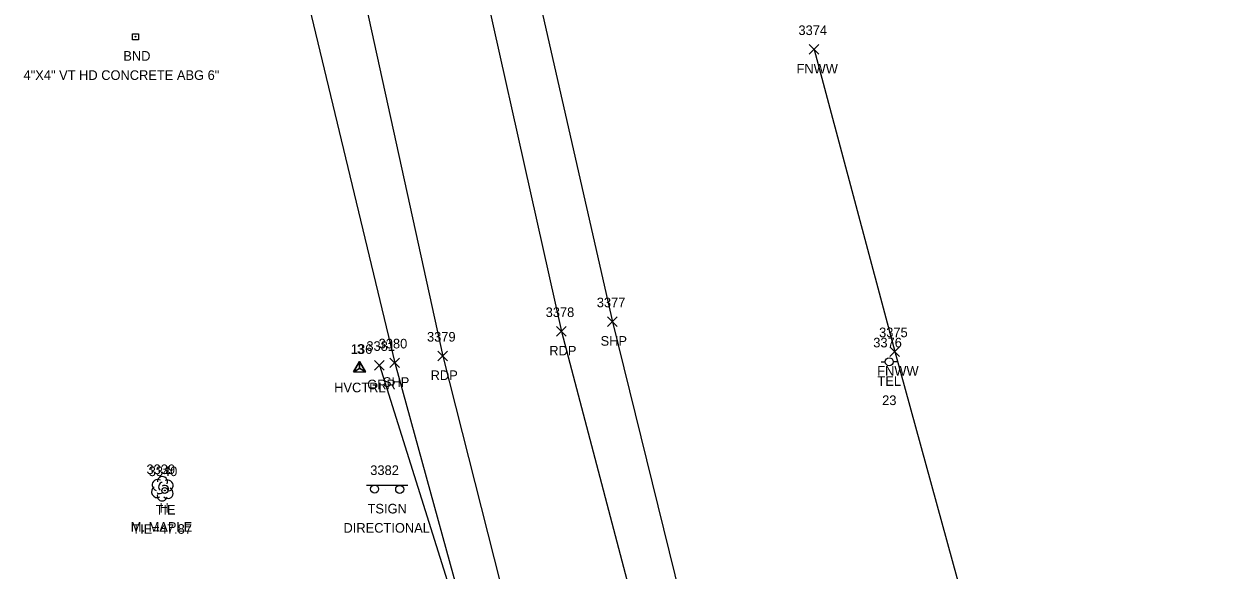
# Model space of a CAD drawing. Extents: x 1443071 to 1445292, y 614024 to 622563.
# Drawn here: x 1444456.9 to 1444705, y 615329.4 to 615443 of the extents above; entities that cross this region are included whole.
import ezdxf

# ---------------------------------------------------------------- set-up
doc = ezdxf.new("R2010")
doc.units = 0
for name, color, linetype in [('C_A', 7, 'Continuous'), ('C_C', 7, 'Continuous'), ('C_I', 7, 'Continuous'), ('CBP', 7, 'Continuous'), ('CPSM', 7, 'Continuous'), ('L_A', 7, 'Continuous'), ('L_C', 7, 'Continuous'), ('L_I', 7, 'Continuous'), ('L_TIC', 7, 'Continuous'), ('LFNC', 7, 'Continuous'), ('LTD', 7, 'Continuous'), ('M_A', 7, 'Continuous'), ('M_C', 7, 'Continuous'), ('MHBP', 7, 'Continuous'), ('P_A', 7, 'Continuous'), ('P_I', 7, 'Continuous'), ('P_TIC', 7, 'Continuous'), ('PET', 7, 'Continuous'), ('PSP', 7, 'Continuous'), ('R_A', 7, 'Continuous'), ('R_I', 7, 'Continuous'), ('R_TIC', 7, 'Continuous'), ('RGR', 7, 'Continuous'), ('S_A', 7, 'Continuous'), ('S_C', 7, 'Continuous'), ('S_I', 7, 'Continuous'), ('SSGN', 7, 'Continuous'), ('U_A', 7, 'Continuous'), ('U_C', 7, 'Continuous'), ('U_I', 7, 'Continuous'), ('UP', 7, 'Continuous')]:
    doc.layers.add(name, color=color, linetype=linetype)

msp = doc.modelspace()

# ---------------------------------------------------------------- linework, layer by layer
at = {"layer": 'CBP'}
for radius in [0.625, 0.0833]:
    msp.add_circle((1444486.26, 615345.94), radius, dxfattribs=at)
at = {"layer": 'CPSM'}
for p, q in [((1444525.55, 615370.66), (1444526.8, 615372.82)), ((1444525.55, 615370.66), (1444526.8, 615371.38)), ((1444525.57, 615370.66), (1444526.82, 615372.82)), ((1444525.57, 615370.66), (1444526.82, 615371.38)), ((1444528.05, 615370.66), (1444526.8, 615372.82)), ((1444526.8, 615371.38), (1444526.8, 615372.82)), ((1444526.8, 615371.38), (1444526.8, 615371.38)), ((1444526.8, 615371.38), (1444528.05, 615370.66)), ((1444528.07, 615370.66), (1444526.82, 615372.82)), ((1444526.82, 615371.38), (1444526.82, 615372.82)), ((1444526.82, 615371.38), (1444526.82, 615371.38)), ((1444526.82, 615371.38), (1444528.07, 615370.66)), ((1444525.55, 615370.66), (1444528.05, 615370.66)), ((1444525.57, 615370.66), (1444528.07, 615370.66))]:
    msp.add_line(p, q, dxfattribs=at)
at = {"layer": 'L_TIC'}
for points in [[(1444620.37, 615436.71), (1444622.37, 615438.71)], [(1444622.37, 615436.71), (1444620.37, 615438.71)], [(1444637.15, 615373.84), (1444639.15, 615375.84)], [(1444639.15, 615373.84), (1444637.15, 615375.84)]]:
    msp.add_lwpolyline(points, dxfattribs=at)
at = {"layer": 'LFNC'}
msp.add_lwpolyline([(1444621.37, 615437.71), (1444638.15, 615374.84), (1444654.37, 615315.72), (1444673.95, 615252.52), (1444691.33, 615200.58), (1444701.12, 615169.21), (1444682.74, 615145.08)], dxfattribs=at)
at = {"layer": 'LTD'}
msp.add_line((1444485.72, 615346.36), (1444485.72, 615346.36), dxfattribs=at)
msp.add_line((1444485.72, 615346.36), (1444485.72, 615346.36), dxfattribs=at)
msp.add_arc((1444485.77, 615347.79), 1.05, 335.5272, 180.9563, dxfattribs=at)
for centre, major_axis, ratio, start_param, end_param in [((1444484.64, 615345.65), (0.58, -1.04), 0.959034, 3.141593, 6.283185), ((1444484.93, 615347.02), (1.21, -0.51), 0.895232, 1.570796, 4.712389), ((1444485.51, 615346.81), (-0.208, -0.792), 0.645439, 3.141593, 6.283185), ((1444486.22, 615346.19), (-0.5, 0.667), 0.989748, 3.141593, 6.283185), ((1444486.72, 615345.52), (-1.09, 0.79), 0.841452, 1.570796, 4.712389), ((1444486.76, 615346.94), (-1.14, -0.48), 0.949671, 1.570796, 4.712389), ((1444485.72, 615344.86), (0.26, 1.06), 0.942809, 1.570796, 4.712389), ((1444485.26, 615345.61), (-0.625, -0.083), 0.423636, 0, 3.141593)]:
    msp.add_ellipse(centre, major_axis=major_axis, ratio=ratio, start_param=start_param, end_param=end_param, dxfattribs=at)
at = {"layer": 'MHBP'}
msp.add_lwpolyline([(1444479.51, 615440.99), (1444480.76, 615440.99), (1444480.76, 615439.74), (1444479.51, 615439.74)], close=True, dxfattribs=at)
msp.add_circle((1444480.14, 615440.37), 0.0833, dxfattribs=at)
at = {"layer": 'P_TIC'}
for points in [[(1444578.41, 615380.07), (1444580.41, 615382.07)], [(1444580.41, 615380.07), (1444578.41, 615382.07)], [(1444567.77, 615378.04), (1444569.77, 615380.04)], [(1444569.77, 615378.04), (1444567.77, 615380.04)], [(1444533.11, 615371.51), (1444535.11, 615373.51)], [(1444535.11, 615371.51), (1444533.11, 615373.51)], [(1444543.09, 615372.93), (1444545.09, 615374.93)], [(1444545.09, 615372.93), (1444543.09, 615374.93)]]:
    msp.add_lwpolyline(points, dxfattribs=at)
at = {"layer": 'PET'}
for points in [[(1444515.41, 615666.64), (1444525.64, 615597.72), (1444539.15, 615516.88), (1444546.82, 615477.47), (1444568.77, 615379.04), (1444586.53, 615311.53), (1444610.33, 615232.54), (1444627.09, 615182.96), (1444651.76, 615115.59), (1444677.88, 615049.92), (1444706.69, 614984.38), (1444728.43, 614937.95), (1444768.51, 614858.7), (1444799.15, 614800.99), (1444824.62, 614757.18), (1444865.42, 614691.8), (1444899.77, 614641.45), (1444937.88, 614589.68), (1444998.28, 614514.87), (1445051.44, 614455.88), (1445114.13, 614386.03), (1445184.96, 614305.48), (1445233, 614249.8)], [(1444490.82, 615663.43), (1444501.1, 615593.99), (1444515.27, 615511.62), (1444521.19, 615478.35), (1444544.09, 615373.93), (1444561.44, 615305.44), (1444586.48, 615224.03), (1444602.94, 615175.46), (1444627.39, 615107.06), (1444650.85, 615039.44), (1444675.64, 614974.55), (1444696.75, 614924.47), (1444735.13, 614842.55), (1444765.29, 614784.89)]]:
    msp.add_lwpolyline(points, dxfattribs=at)
at = {"layer": 'PSP'}
for points in [[(1444525.85, 615667.7), (1444535.69, 615600.77), (1444549.66, 615520.08), (1444553.54, 615501.93), (1444563.5, 615450.95), (1444579.41, 615381.07), (1444595.9, 615314.06), (1444619.24, 615236.14), (1444635.55, 615185.75), (1444659.46, 615119.95), (1444685.78, 615053.56), (1444714.86, 614987.25), (1444736.37, 614941.29), (1444776.12, 614863.57), (1444806.96, 614805.44), (1444831.81, 614763.27), (1444872.68, 614696.13), (1444906.86, 614647.72), (1444944.43, 614594.03), (1445004.77, 614520.62), (1445058.5, 614460.6), (1445120.25, 614392.35), (1445191.33, 614311.4), (1445239.24, 614255.89)], [(1444481.34, 615661.86), (1444491.6, 615592.34), (1444495.53, 615565.58), (1444502, 615519.06), (1444506.81, 615495.93), (1444514.08, 615455.86), (1444534.11, 615372.51), (1444552.93, 615304.11), (1444577.65, 615221.25), (1444593.68, 615173.12), (1444618.66, 615104.72), (1444644.27, 615037.2), (1444671.31, 614972.18), (1444691.69, 614923.2), (1444732.4, 614840.77), (1444762.04, 614783.35)]]:
    msp.add_lwpolyline(points, dxfattribs=at)
at = {"layer": 'R_TIC'}
for points in [[(1444529.9, 615371), (1444531.9, 615373)], [(1444531.9, 615371), (1444529.9, 615373)]]:
    msp.add_lwpolyline(points, dxfattribs=at)
at = {"layer": 'RGR'}
msp.add_lwpolyline([(1444530.9, 615372), (1444552.25, 615304.24), (1444576.9, 615221.66), (1444593.27, 615173.01), (1444618.09, 615104.36), (1444643.94, 615037.22), (1444670.66, 614971.69), (1444687.9, 614922.59)], dxfattribs=at)
at = {"layer": 'SSGN'}
for p, q in [((1444528.25, 615347.09), (1444536.85, 615347.09)), ((1444532.28, 615346.18), (1444532.28, 615346.18))]:
    msp.add_line(p, q, dxfattribs=at)
for centre in [(1444529.91, 615346.25), (1444535.13, 615346.18)]:
    msp.add_circle(centre, 0.833, dxfattribs=at)
at = {"layer": 'UP'}
for p, q in [((1444635.34, 615372.71), (1444636.16, 615372.71)), ((1444637, 615372.72), (1444637, 615372.72)), ((1444638.66, 615372.72), (1444637.83, 615372.72)), ((1444637.83, 615372.72), (1444637.83, 615372.72)), ((1444638.66, 615372.72), (1444638.66, 615372.72))]:
    msp.add_line(p, q, dxfattribs=at)
msp.add_circle((1444637, 615372.72), 0.833, dxfattribs=at)

# ---------------------------------------------------------------- texts
at = {"layer": 'C_A'}
for s, p in [('HVCTRL', (1444521.5, 615366.38)), ('HVCTRL', (1444521.51, 615366.38)), ('TIE', (1444484.34, 615340.94))]:
    msp.add_text(s, height=2, dxfattribs=at).set_placement(p)
at = {"layer": 'C_C'}
msp.add_text('TIE=47.87', height=2, dxfattribs=at).set_placement((1444479.49, 615336.94))
at = {"layer": 'C_I'}
for s, p in [('136', (1444524.97, 615374.38)), ('3', (1444526.24, 615374.38)), ('3340', (1444482.91, 615348.94))]:
    msp.add_text(s, height=2, dxfattribs=at).set_placement(p)
at = {"layer": 'L_A'}
for s, p in [('FNWW', (1444617.71, 615432.71)), ('FNWW', (1444634.5, 615369.84)), ('H', (1444485.15, 615341.36))]:
    msp.add_text(s, height=2, dxfattribs=at).set_placement(p)
at = {"layer": 'L_C'}
msp.add_text('M. MAPLE', height=2, dxfattribs=at).set_placement((1444479.17, 615337.36))
at = {"layer": 'L_I'}
for s, p in [('3374', (1444618.11, 615440.71)), ('3375', (1444634.89, 615377.84)), ('3339', (1444482.45, 615349.36))]:
    msp.add_text(s, height=2, dxfattribs=at).set_placement(p)
at = {"layer": 'M_A'}
msp.add_text('BND', height=2, dxfattribs=at).set_placement((1444477.63, 615435.37))
at = {"layer": 'M_C'}
msp.add_text('4"X4" VT HD CONCRETE ABG 6"', height=2, dxfattribs=at).set_placement((1444456.86, 615431.37))
at = {"layer": 'P_A'}
for s, p in [('RDP', (1444566.26, 615374.04)), ('SHP', (1444576.94, 615376.07)), ('RDP', (1444541.57, 615368.93)), ('SHP', (1444531.64, 615367.51))]:
    msp.add_text(s, height=2, dxfattribs=at).set_placement(p)
at = {"layer": 'P_I'}
for s, p in [('3377', (1444576.15, 615384.07)), ('3378', (1444565.51, 615382.04)), ('3379', (1444540.82, 615376.93)), ('3380', (1444530.76, 615375.51))]:
    msp.add_text(s, height=2, dxfattribs=at).set_placement(p)
at = {"layer": 'R_A'}
msp.add_text('GRR', height=2, dxfattribs=at).set_placement((1444528.38, 615367))
at = {"layer": 'R_I'}
msp.add_text('3381', height=2, dxfattribs=at).set_placement((1444528.2, 615375))
at = {"layer": 'S_A'}
msp.add_text('TSIGN', height=2, dxfattribs=at).set_placement((1444528.45, 615341.17))
at = {"layer": 'S_C'}
msp.add_text('DIRECTIONAL', height=2, dxfattribs=at).set_placement((1444523.44, 615337.17))
at = {"layer": 'S_I'}
msp.add_text('3382', height=2, dxfattribs=at).set_placement((1444529.01, 615349.17))
at = {"layer": 'U_A'}
msp.add_text('TEL', height=2, dxfattribs=at).set_placement((1444634.55, 615367.72))
at = {"layer": 'U_C'}
msp.add_text('23', height=2, dxfattribs=at).set_placement((1444635.53, 615363.72))
at = {"layer": 'U_I'}
msp.add_text('3376', height=2, dxfattribs=at).set_placement((1444633.68, 615375.72))

doc.saveas('drawing.dxf')
